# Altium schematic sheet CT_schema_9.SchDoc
size 274 x 160 mm
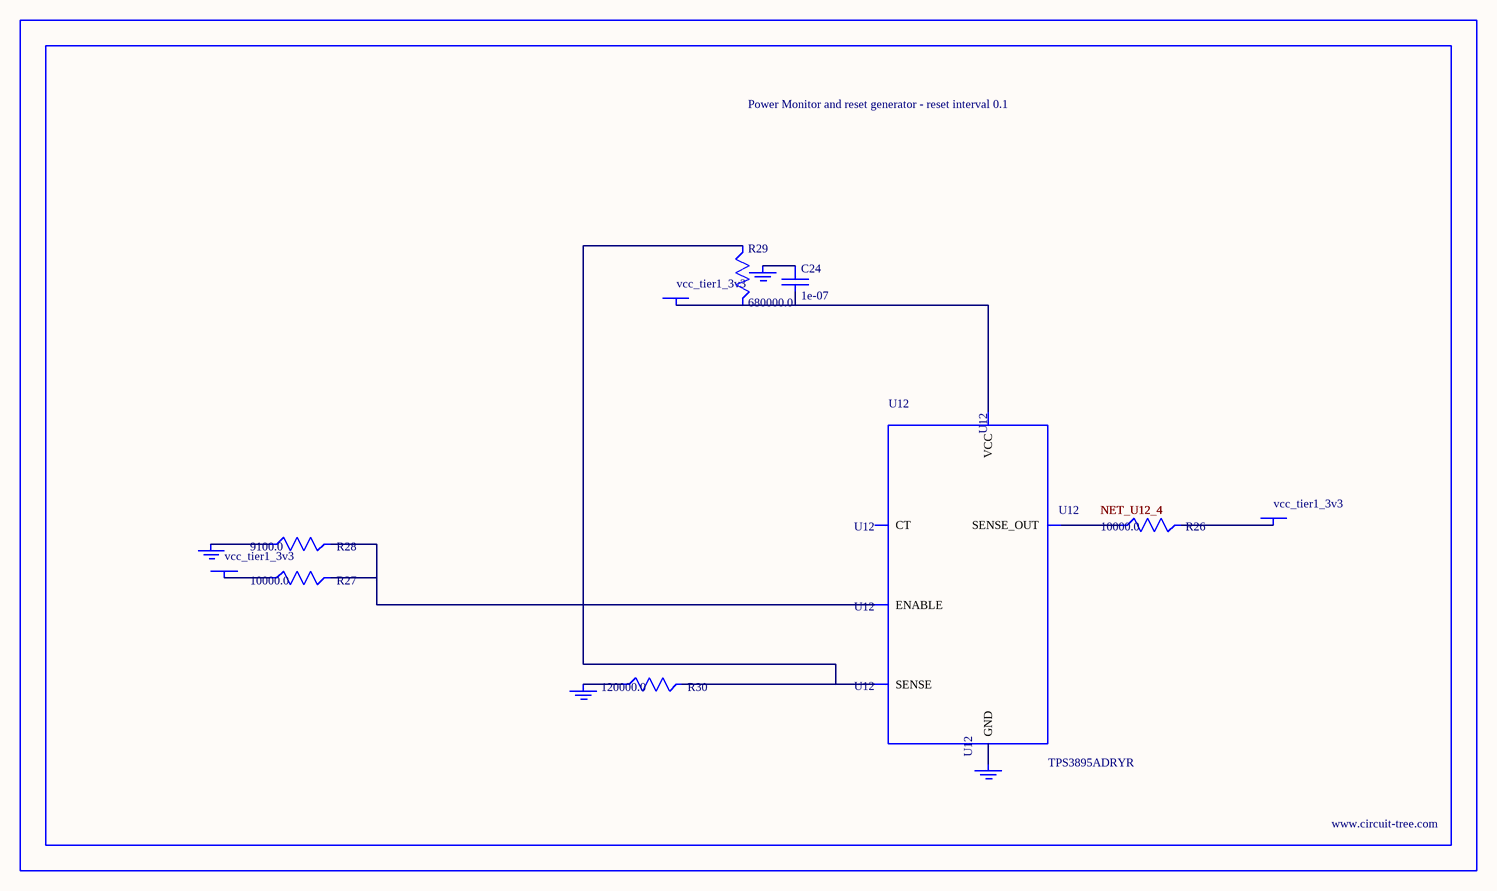
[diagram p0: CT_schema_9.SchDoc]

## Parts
BORDER8  (no value)
C24  1e-07  [C0402]
GND_INSTANCE_8_0  (no value)
GND_INSTANCE_8_1  (no value)
GND_INSTANCE_8_2  (no value)
GND_INSTANCE_8_3  (no value)
POWER_INSTANCE_8_0  vcc_tier1_3v3
POWER_INSTANCE_8_1  vcc_tier1_3v3
POWER_INSTANCE_8_2  vcc_tier1_3v3
R26  10000.0  [R0603]
R27  10000.0  [R0603]
R28  9100.0  [R0603]
R29  680000.0  [R0603]
R30  120000.0  [R0603]
U12  TPS3895ADRYR  [SON-6]

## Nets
NetC24_1: C24.1 GND_INSTANCE_8_2.0(GND)
NetC24_2: C24.2 POWER_INSTANCE_8_2.0(PWR) R29.2 U12.6(VCC)
NetGND_INSTANCE_8_0_0: GND_INSTANCE_8_0.0(GND) R28.1
NetGND_INSTANCE_8_1_0: GND_INSTANCE_8_1.0(GND) R30.1
NetGND_INSTANCE_8_3_0: GND_INSTANCE_8_3.0(GND) U12.2(GND)
NetPOWER_INSTANCE_8_0_0: POWER_INSTANCE_8_0.0(PWR) R27.1
NetPOWER_INSTANCE_8_1_0: POWER_INSTANCE_8_1.0(PWR) R26.2
NetR26_1: R26.1 U12.4(SENSE_OUT)
NetR27_2: R27.2 R28.2 U12.1(ENABLE)
NetR29_1: R29.1 R30.2 U12.3(SENSE)

Not connected (* = marked no-connect by the designer): U12 5(CT)

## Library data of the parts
BORDER8 = BORDER_PAGE8
C24 = C0402C104K3RACTU
GND_INSTANCE_8_0-GND_INSTANCE_8_3 = GND
POWER_INSTANCE_8_0-POWER_INSTANCE_8_2 = PWR
R26 R27 = RC0603JR-0710KL
R28 = RC0603JR-079K1L
R29 = RC0603JR-07680KL
R30 = RC0603JR-07120KL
